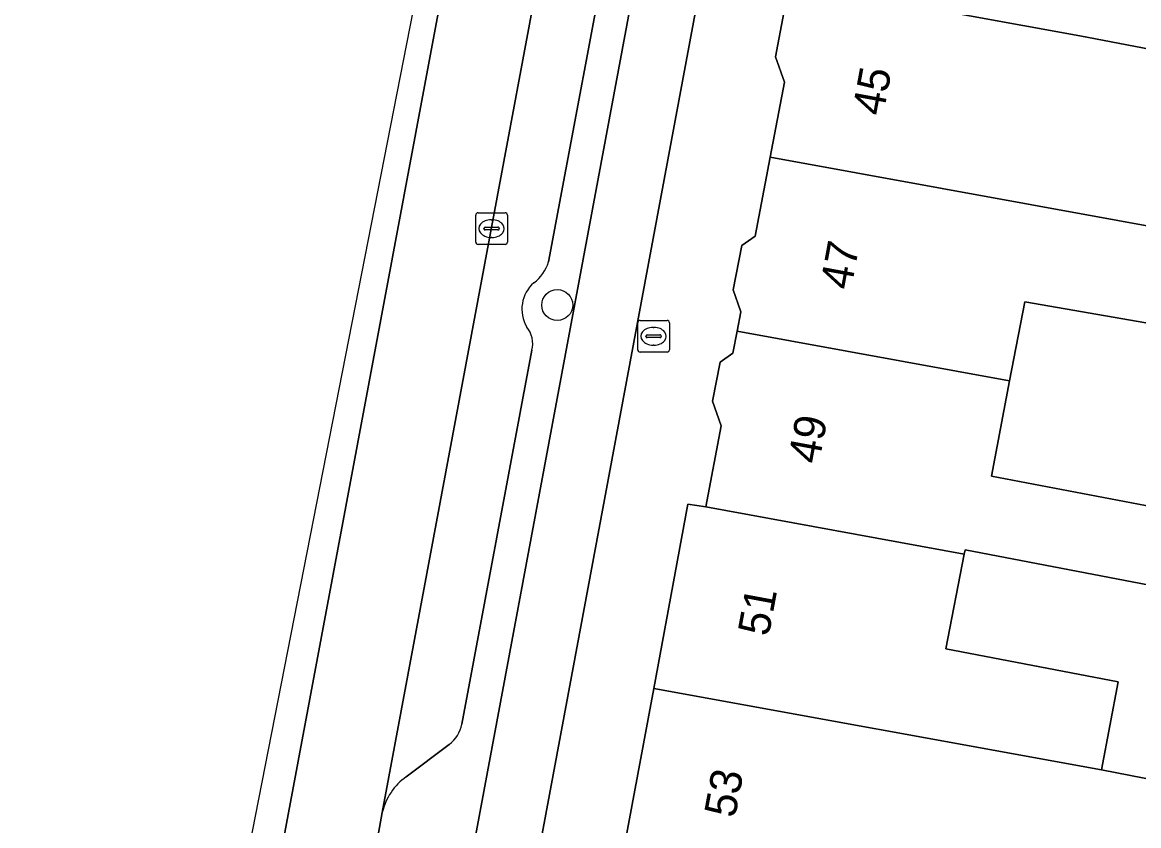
# Model space of a CAD drawing. Extents: x 161838 to 162344, y 381620 to 382160.
# Drawn here: x 161893.72 to 161929.05, y 381954.06 to 381979.46 of the extents above; entities that cross this region are included whole.
import ezdxf

# ---------------------------------------------------------------- set-up
doc = ezdxf.new("R2010")
doc.units = 0
for name, color, linetype in [('IMGEO_Berm_open', 7, 'Continuous'), ('IMGEO_Boom', 7, 'Continuous'), ('IMGEO_Brandkraan', 7, 'Continuous'), ('IMGEO_Erf', 7, 'Continuous'), ('IMGEO_Fietspad_gesloten', 7, 'Continuous'), ('IMGEO_Kolk', 7, 'Continuous'), ('IMGEO_OVBaan_gesloten', 7, 'Continuous'), ('IMGEO_Pand', 7, 'Continuous'), ('IMGEO_Pand_nummerreeks', 7, 'Continuous'), ('IMGEO_Parkeervlak_open', 7, 'Continuous'), ('IMGEO_Rijbaan_lokaal_gesloten', 7, 'Continuous'), ('IMGEO_Voetpad_open', 7, 'Continuous')]:
    doc.layers.add(name, color=color, linetype=linetype)

msp = doc.modelspace()

# ---------------------------------------------------------------- linework, layer by layer
at = {"layer": 'IMGEO_Berm_open'}
for points in [[(161897.858, 381899.101), (161916.698, 382000), (161921.558, 382026.031), (161926.346, 382051.921)], [(161912.327, 381984.161), (161912.529, 381983.412), (161910.367, 381971.885)], [(161909.841, 381969.093), (161907.627, 381957.272)], [(161907.226, 381956.627), (161905.868, 381955.605)], [(161905.11, 381954.479), (161905.076, 381954.299), (161904.686, 381952.125), (161903.787, 381947.27), (161902.001, 381937.624), (161901.082, 381932.662), (161899.202, 381922.742)]]:
    msp.add_lwpolyline(points, dxfattribs=at)
for centre, radius, start, end in [((161909.157, 381972.242), 1.262, 306.5409, 343.5805), ((161910.639, 381970.389), 1.112, 131.0675, 210.3662), ((161909.065, 381969.307), 0.805, 344.5994, 40.2929), ((161906.596, 381957.466), 1.049, 306.8979, 349.3632), ((161906.979, 381954.039), 1.92, 125.3481, 166.7566)]:
    msp.add_arc(centre, radius, start, end, dxfattribs=at)
at = {"layer": 'IMGEO_Boom'}
msp.add_circle((161910.646, 381970.522), 0.489, dxfattribs=at)
at = {"layer": 'IMGEO_Brandkraan'}
for p, q in [((161913.194, 381969.108), (161913.194, 381969.96)), ((161913.269, 381970.034), (161914.121, 381970.034)), ((161913.682, 381969.814), (161913.707, 381969.814)), ((161914.195, 381969.96), (161914.195, 381969.108)), ((161913.453, 381969.528), (161913.453, 381969.54)), ((161913.891, 381969.491), (161913.493, 381969.491)), ((161913.496, 381969.577), (161913.894, 381969.577)), ((161913.937, 381969.54), (161913.937, 381969.528)), ((161913.705, 381969.254), (161913.68, 381969.254)), ((161914.121, 381969.034), (161913.269, 381969.034))]:
    msp.add_line(p, q, dxfattribs=at)
for points in [[(161913.194, 381969.108), (161913.194, 381969.96)], [(161913.269, 381970.034), (161914.121, 381970.034)], [(161914.195, 381969.96), (161914.195, 381969.108)], [(161914.121, 381969.034), (161913.269, 381969.034)]]:
    msp.add_lwpolyline(points, dxfattribs=at)
for centre, radius, start, end in [((161913.271, 381969.958), 0.0765, 91.552, 178.448), ((161913.271, 381969.958), 0.0765, 91.552, 178.448), ((161914.119, 381969.958), 0.0765, 1.552, 88.448), ((161914.119, 381969.958), 0.0765, 1.552, 88.448), ((161913.493, 381969.537), 0.0403, 85.8775, 175.7526), ((161913.49, 381969.527), 0.0366, 178.938, 274.7102), ((161913.894, 381969.534), 0.043, 264.8664, 352.4533), ((161913.898, 381969.539), 0.0386, 1.7309, 96.639), ((161913.271, 381969.11), 0.0765, 181.552, 268.448), ((161913.271, 381969.11), 0.0765, 181.552, 268.448), ((161914.119, 381969.11), 0.0765, 271.552, 358.448), ((161914.119, 381969.11), 0.0765, 271.552, 358.448)]:
    msp.add_arc(centre, radius, start, end, dxfattribs=at)
for centre, major_axis, ratio, start_param, end_param in [((161913.681, 381969.534), (-0.387, 0.002), 0.722429, 4.712389, 7.853982), ((161913.706, 381969.534), (-0.39, 0.002), 0.717154, 1.570796, 4.712389)]:
    msp.add_ellipse(centre, major_axis=major_axis, ratio=ratio, start_param=start_param, end_param=end_param, dxfattribs=at)
at = {"layer": 'IMGEO_Erf'}
msp.add_lwpolyline([(161945.272, 381983.095), (161943.88, 381975.836), (161932.143, 381978.085), (161931.602, 381975.251), (161931.115, 381972.699), (161930.551, 381969.74), (161925.442, 381970.627), (161924.965, 381968.124), (161924.391, 381965.113), (161929.484, 381964.142), (161929.96, 381964.051), (161934.143, 381963.254), (161933.683, 381960.843), (161923.552, 381962.781), (161923.526, 381962.648), (161922.949, 381959.647), (161928.403, 381958.607), (161927.872, 381955.818), (161935.487, 381954.336), (161936.573, 381960.29), (161940.551, 381959.529), (161942.497, 381970.209), (161946.353, 381969.488), (161960.778, 381966.791)], dxfattribs=at)
at = {"layer": 'IMGEO_Fietspad_gesloten'}
for points in [[(161897.095, 381883.929), (161899.866, 381898.705), (161907.39, 381938.834), (161908.427, 381944.469), (161918.786, 382000), (161923.625, 382025.943), (161928.95, 382054.459)], [(161926.346, 382051.921), (161921.558, 382026.031), (161916.698, 382000), (161897.858, 381899.101), (161895.081, 381884.229), (161870.207, 381751.91), (161869.854, 381750), (161864.774, 381722.548), (161862.987, 381712.892), (161857.316, 381682.246)]]:
    msp.add_lwpolyline(points, dxfattribs=at)
at = {"layer": 'IMGEO_Kolk'}
for p, q in [((161908.067, 381972.513), (161908.067, 381973.365)), ((161908.142, 381973.439), (161908.994, 381973.439)), ((161909.068, 381973.365), (161909.068, 381972.513)), ((161908.369, 381972.982), (161908.767, 381972.982)), ((161908.555, 381973.219), (161908.58, 381973.219)), ((161908.326, 381972.933), (161908.326, 381972.945)), ((161908.764, 381972.896), (161908.366, 381972.896)), ((161908.578, 381972.659), (161908.553, 381972.659)), ((161908.81, 381972.945), (161908.81, 381972.933)), ((161908.994, 381972.439), (161908.142, 381972.439))]:
    msp.add_line(p, q, dxfattribs=at)
for points in [[(161908.067, 381972.513), (161908.067, 381973.365)], [(161908.142, 381973.439), (161908.994, 381973.439)], [(161909.068, 381973.365), (161909.068, 381972.513)], [(161908.994, 381972.439), (161908.142, 381972.439)]]:
    msp.add_lwpolyline(points, dxfattribs=at)
for centre, radius, start, end in [((161908.144, 381973.363), 0.0765, 91.552, 178.448), ((161908.144, 381973.363), 0.0765, 91.552, 178.448), ((161908.992, 381973.363), 0.0765, 1.552, 88.448), ((161908.992, 381973.363), 0.0765, 1.552, 88.448), ((161908.366, 381972.942), 0.0403, 85.8775, 175.7526), ((161908.771, 381972.944), 0.0386, 1.7309, 96.639), ((161908.363, 381972.932), 0.0366, 178.938, 274.7102), ((161908.767, 381972.939), 0.043, 264.8664, 352.4533), ((161908.144, 381972.515), 0.0765, 181.552, 268.448), ((161908.144, 381972.515), 0.0765, 181.552, 268.448), ((161908.992, 381972.515), 0.0765, 271.552, 358.448), ((161908.992, 381972.515), 0.0765, 271.552, 358.448)]:
    msp.add_arc(centre, radius, start, end, dxfattribs=at)
for centre, major_axis, ratio, start_param, end_param in [((161908.554, 381972.939), (-0.387, 0.002), 0.722429, 4.712389, 7.853982), ((161908.579, 381972.939), (-0.39, 0.002), 0.717154, 1.570796, 4.712389)]:
    msp.add_ellipse(centre, major_axis=major_axis, ratio=ratio, start_param=start_param, end_param=end_param, dxfattribs=at)
at = {"layer": 'IMGEO_OVBaan_gesloten'}
msp.add_lwpolyline([(161858.651, 381720.96), (161859.425, 381726.158), (161861.132, 381736.231), (161869.606, 381781.344), (161897.211, 381928.16), (161915.531, 382025.949), (161915.767, 382027.092), (161920.812, 382054.098), (161923.657, 382069.694), (161925.944, 382081.248), (161931.886, 382108.929), (161933.831, 382119.131), (161934.302, 382121.796), (161934.443, 382123.117), (161933.101, 382124.399), (161916.93, 382035.129), (161911.481, 382007.357), (161883.773, 381866.122), (161869.795, 381786.79), (161847.814, 381679.325), (161847.327, 381677.629)], dxfattribs=at)
at = {"layer": 'IMGEO_Pand'}
for points in [[(161919.709, 381987.825), (161919.142, 381984.851), (161918.692, 381984.545), (161918.461, 381983.334), (161918.749, 381982.507), (161918.393, 381980.636), (161927.19, 381979.035), (161932.143, 381978.085), (161943.88, 381975.836), (161945.272, 381983.095)], [(161932.143, 381978.085), (161927.19, 381979.035), (161918.393, 381980.636), (161918.288, 381980.086), (161917.819, 381979.768), (161917.554, 381978.377), (161917.835, 381977.569), (161917.384, 381975.201), (161931.115, 381972.699), (161931.602, 381975.251)], [(161916.341, 381969.695), (161924.965, 381968.124), (161925.442, 381970.627), (161930.551, 381969.74), (161931.115, 381972.699), (161917.384, 381975.201), (161916.906, 381972.696), (161916.486, 381972.41), (161916.217, 381971.001), (161916.458, 381970.311)], [(161924.965, 381968.124), (161916.341, 381969.695), (161916.207, 381968.995), (161915.801, 381968.718), (161915.565, 381967.483), (161915.837, 381966.701), (161915.349, 381964.138), (161923.526, 381962.648), (161923.552, 381962.781), (161933.683, 381960.843), (161934.143, 381963.254), (161929.96, 381964.051), (161929.484, 381964.142), (161924.391, 381965.113)], [(161927.872, 381955.818), (161928.403, 381958.607), (161922.949, 381959.647), (161923.526, 381962.648), (161915.349, 381964.138), (161914.782, 381964.23), (161913.7, 381958.4)], [(161936.114, 381954.214), (161935.487, 381954.336), (161927.872, 381955.818), (161913.7, 381958.4), (161912.693, 381952.972), (161935.086, 381948.574)]]:
    msp.add_lwpolyline(points, close=True, dxfattribs=at)
at = {"layer": 'IMGEO_Parkeervlak_open'}
for points in [[(161917.608, 382021.312), (161913.622, 382000), (161905.11, 381954.479)], [(161910.367, 381971.885), (161912.529, 381983.412), (161912.327, 381984.161)], [(161907.627, 381957.272), (161909.841, 381969.093)], [(161905.868, 381955.605), (161907.226, 381956.627)]]:
    msp.add_lwpolyline(points, dxfattribs=at)
for centre, radius, start, end in [((161909.157, 381972.242), 1.262, 306.5409, 343.5805), ((161910.639, 381970.389), 1.112, 131.0675, 210.3662), ((161909.065, 381969.307), 0.805, 344.5994, 40.2929), ((161906.596, 381957.466), 1.049, 306.8979, 349.3632), ((161906.979, 381954.039), 1.92, 125.3481, 166.7566)]:
    msp.add_arc(centre, radius, start, end, dxfattribs=at)
at = {"layer": 'IMGEO_Rijbaan_lokaal_gesloten'}
for points in [[(161918.789, 382041.718), (161915.767, 382027.092), (161915.531, 382025.949), (161897.211, 381928.16), (161869.606, 381781.344), (161861.132, 381736.231), (161859.425, 381726.158), (161858.651, 381720.96)], [(161862.533, 381727.211), (161866.175, 381746.944), (161866.739, 381750), (161866.904, 381750.735), (161870.759, 381771.481), (161871.456, 381775.156), (161894.868, 381899.69), (161899.202, 381922.742), (161901.082, 381932.662), (161902.001, 381937.624), (161903.787, 381947.27), (161904.686, 381952.125), (161905.076, 381954.299), (161905.11, 381954.479), (161913.622, 382000), (161917.608, 382021.312), (161917.651, 382021.542), (161920.351, 382034.502), (161920.367, 382034.753)]]:
    msp.add_lwpolyline(points, dxfattribs=at)
at = {"layer": 'IMGEO_Voetpad_open'}
for points in [[(161928.95, 382054.459), (161923.625, 382025.943), (161918.786, 382000), (161908.427, 381944.469)], [(161910.886, 381943.394), (161912.446, 381947.826), (161911.942, 381948.927), (161912.693, 381952.972), (161913.7, 381958.4), (161914.782, 381964.23), (161915.349, 381964.138), (161915.837, 381966.701), (161915.565, 381967.483), (161915.801, 381968.718), (161916.207, 381968.995), (161916.341, 381969.695), (161916.458, 381970.311), (161916.217, 381971.001), (161916.486, 381972.41), (161916.906, 381972.696), (161917.384, 381975.201), (161917.835, 381977.569), (161917.554, 381978.377), (161917.819, 381979.768)]]:
    msp.add_lwpolyline(points, dxfattribs=at)

# ---------------------------------------------------------------- texts
at = {"layer": 'IMGEO_Pand_nummerreeks'}
for s, rotation, p in [('45', 79.5459, (161920.96, 381976.476)), ('47', 79.5459, (161919.944, 381970.972)), ('49', 79.5437, (161918.929, 381965.467)), ('51', 79.486, (161917.335, 381960.016)), ('53', 79.4864, (161916.272, 381954.275))]:
    msp.add_text(s, height=1, rotation=rotation, dxfattribs=at).set_placement(p)

doc.saveas('drawing.dxf')
